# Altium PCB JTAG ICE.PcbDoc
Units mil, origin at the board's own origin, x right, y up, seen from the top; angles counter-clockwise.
Board outline 3085 x 1720 mil, 2 copper layers (Top Layer, Bottom Layer); 45 components, 0 nets, 201 pads, 2 vias.
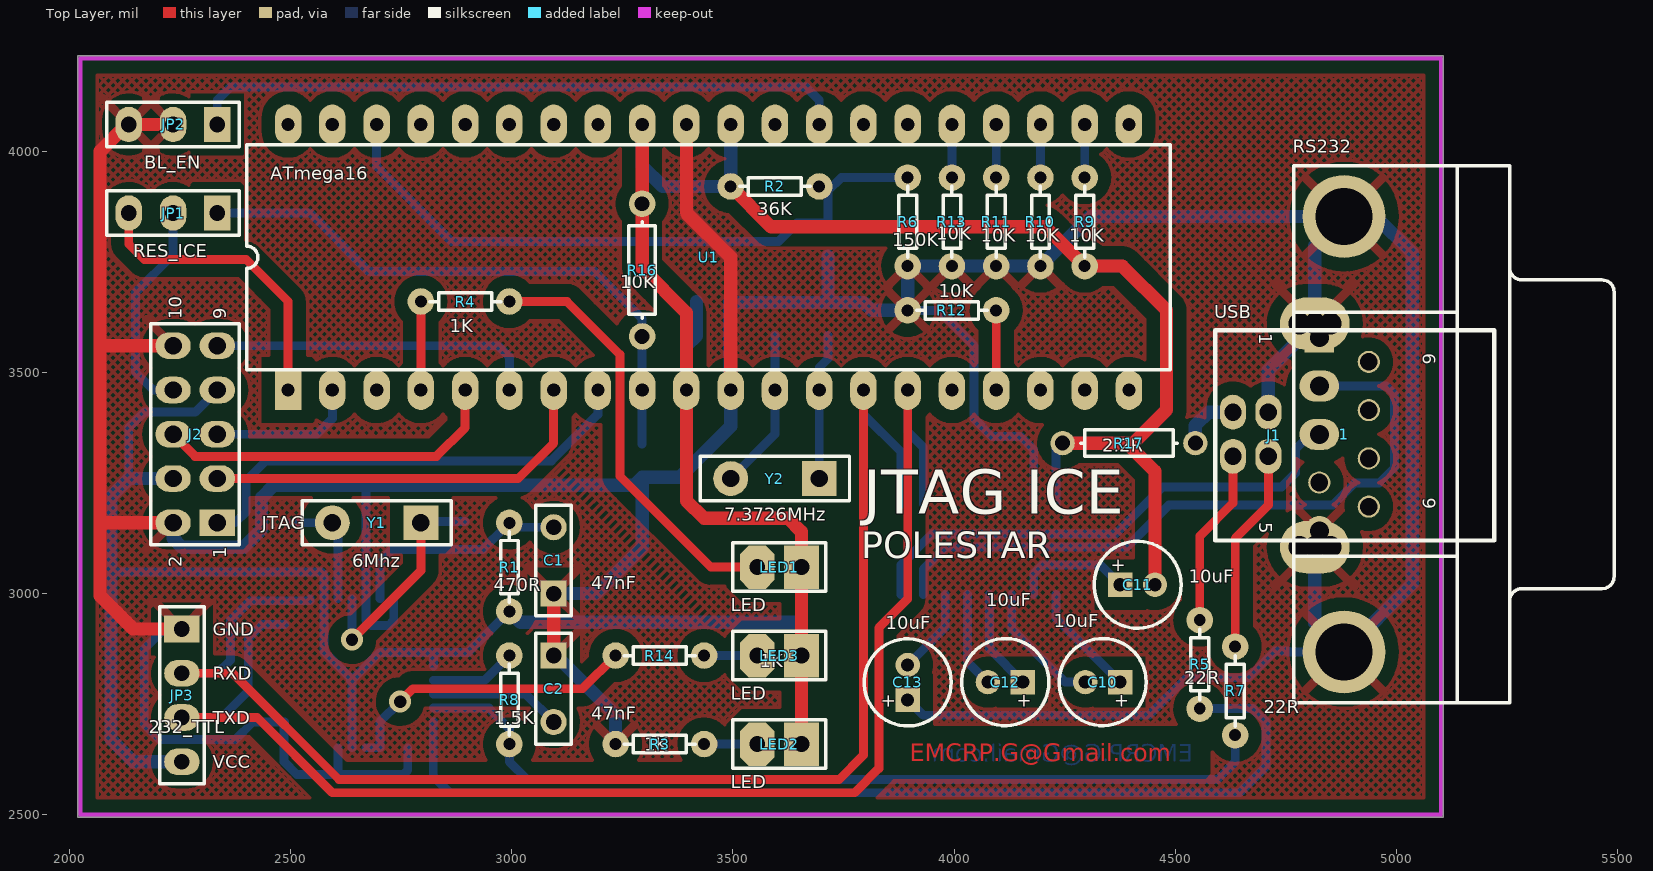
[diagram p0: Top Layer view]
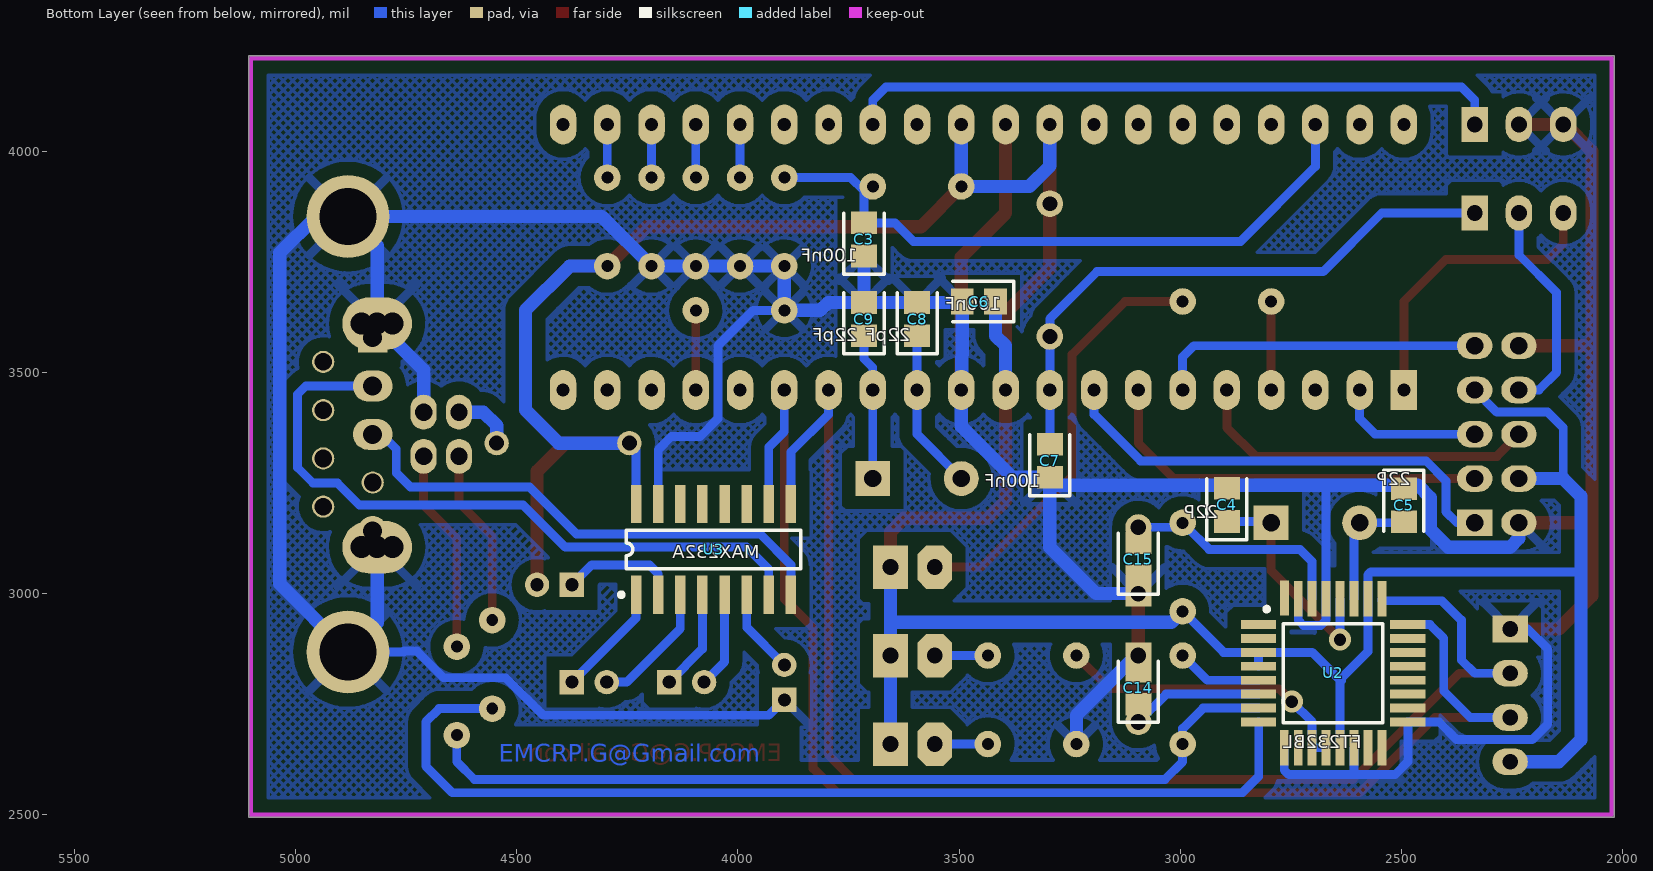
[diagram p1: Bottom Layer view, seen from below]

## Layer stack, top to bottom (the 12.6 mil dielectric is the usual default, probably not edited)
Top Layer: signal copper 1.4
Dielectric: dielectric 12.6, FR-4, Dk 4.8
Bottom Layer: signal copper 1.4

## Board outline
2020,2495 5105,2495 5105,4215 2020,4215

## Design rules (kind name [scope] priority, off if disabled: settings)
Clearance [All] p1: gap=10
PolygonConnect [All] p1: connectstyle=Relief reliefconductorwidth=10 reliefentries=4 polygonreliefangle="90 Angle" airgapwidth=10
RoutingVias [All] p1: holewidth=28 width=50 viastyle="Through Hole" minholewidth=28 minwidth=50 maxholewidth=28 maxwidth=50
SilkscreenOverComponentPads [All] p1: minsilkscreentomaskgap=10
SolderMaskExpansion [All] p1: expansion=4
Width [All] p1: maxlimit=10 minlimit=10 preferedwidth=10
27 further rules are at their usual default settings.

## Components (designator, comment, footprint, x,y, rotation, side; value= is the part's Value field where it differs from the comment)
1 "RS232" DSUB1.385-2H9 5255,3360 r270 top
C1 "47nF" CAP_M_X2 3095,3100 r90 top
C2 "47nF" CAP_M_X2 3095,2760 r270 top
C3 "100nF" CC2012-0805 3715,3800 r90 bottom
C4 "22P" CC2012-0805 2895,3200 r90 bottom
C5 "22P" CC2012-0805 2495,3200 r270 bottom
C6 "100nF" CC2012-0805 3455,3660 r0 bottom
C7 "100nF" CC2012-0805 3295,3300 r90 bottom
C8 "22pF" CC2012-0805 3595,3620 r90 bottom
C9 "22pF" CC2012-0805 3715,3620 r90 bottom
C10 "10uF" CAP_POL1 4375,2800 r180 top
C11 "10uF" CAP_POL1 4375,3020 r0 top
C12 "10uF" CAP_POL1 4155,2800 r180 top
C13 "10uF" CAP_POL1 3895,2760 r90 top
C14 "22pF" CC2012-0805 3095,2787.28 r90 bottom
C15 "47nF" CC2012-0805 3095,3077.28 r90 bottom
J1 "USB" USB_B 5115,3420 r180 top
J2 "JTAG" HDR2X5 2335,3160 r90 top
JP1 "RES_ICE" HDR1X3 2335,3860 r180 top
JP2 "BL_EN" HDR1X3 2335,4060 r180 top
JP3 "232_TTL" HDR1X4 2255,2920 r270 top
LED1 "LED" LED 3655,3060 r180 top
LED2 "LED" LED 3655,2660 r180 top
LED3 "LED" LED 3655,2860 r180 top
R1 "470R" AXIAL-0.2 2995,3060 r270 top
R2 "36K" AXIAL-0.2 3595,3920 r180 top
R3 "1K" AXIAL-0.2 3335,2660 r0 top
R4 "1K" AXIAL-0.2 2895,3660 r0 top
R5 "22R" AXIAL-0.2 4555,2840 r270 top
R6 "150K" AXIAL-0.2 3895,3840 r90 top
R7 "22R" AXIAL-0.2 4635,2780 r270 top
R8 "1.5K" AXIAL-0.2 2995,2760 r90 top
R9 "10K" AXIAL-0.2 4295,3840 r270 top
R10 "10K" AXIAL-0.2 4195,3840 r270 top
R11 "10K" AXIAL-0.2 4095,3840 r270 top
R12 "10K" AXIAL-0.2 3995,3640 r180 top
R13 "10K" AXIAL-0.2 3995,3840 r270 top
R14 "1K" AXIAL-0.2 3335,2860 r180 top
R16 "10K" AXIAL-0.3#1 3295,3680 r90 top
R17 "2.2R" AXIAL-0.3#2 4395,3340 r180 top
U1 "ATmega16" DIP40 3595,4160 r0 top
U2 "FT232BL" 32A 2655,2820 r180 bottom
U3 "MAX232A" NSO16 4055,3100 r180 bottom
Y1 "6Mhz" SPST-2 2695,3160 r180 top
Y2 "7.3726MHz" SPST-2 3595,3260 r180 top

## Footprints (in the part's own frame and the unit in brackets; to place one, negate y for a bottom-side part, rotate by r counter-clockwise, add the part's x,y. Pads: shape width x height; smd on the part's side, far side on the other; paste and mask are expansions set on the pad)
32A [mil]
  rect 80x20 smd: 1(-168.46,110.24) 2(-168.46,78.74) 3(-168.46,47.24) 4(-168.46,15.75) 5(-168.46,-15.75) 6(-168.46,-47.24) 7(-168.46,-78.74) 8(-168.46,-110.24) 17(168.47,-110.24) 18(168.46,-78.74) 19(168.46,-47.24) 20(168.46,-15.75) 21(168.46,15.75) 22(168.46,47.24) 23(168.46,78.74) 24(168.47,110.24)
  rect 20x80 smd: 9(-110.24,-168.46) 10(-78.74,-168.46) 11(-47.24,-168.46) 12(-15.75,-168.46) 13(15.75,-168.46) 14(47.24,-168.46) 15(78.74,-168.46) 16(110.24,-168.46) 25(110.24,168.47) 26(78.74,168.47) 27(47.24,168.47) 28(15.75,168.47) 29(-15.75,168.47) 30(-47.24,168.47) 31(-78.74,168.47) 32(-110,170)
  silkscreen extent -155,-112 112,150
AXIAL-0.2 [mil]
  round 60 hole 27: 1(-100,0) 2(100,0)
  silkscreen extent -80,-20 80,20
AXIAL-0.3#1 [mil]
  round 60 hole 33.47: 1(-99,0) 2(201,0)
  silkscreen extent -58,-30 160,30
AXIAL-0.3#2 [mil]
  round 55.12 hole 33.46: 1(-150,0) 2(150,0)
  silkscreen extent -109,-30 109,30
CAP_M_X2 [mm]
  rect 1.5x1.5 hole 0.9: 1(-2.54,0)
  round 1.5 hole 0.9: 2(1.27,0)
  silkscreen extent -3.81,-1.02 2.54,1.02
CAP_POL1 [mil]
  rect 55x55 hole 29.53: 1(0,0)
  round 55 hole 29.53: 2(78.74,0)
  silkscreen extent -59,-98 138,98
CC2012-0805 [mm]
  rect 1.3x1.5 smd: 1(-0.942,0) 2(0.958,0)
  silkscreen extent -1.99,-1.15 1.51,1.15
DIP40 [mil]
  rect 60x90 hole 30: 1(-1100,-700)
  oval 60x90 hole 30: 2(-1000,-700) 3(-900,-700) 4(-800,-700) 5(-700,-700) 6(-600,-700) 7(-500,-700) 8(-400,-700) 9(-300,-700) 10(-200,-700) 11(-100,-700) 12(0,-700) 13(100,-700) 14(200,-700) 15(300,-700) 16(400,-700) 17(500,-700) 18(600,-700) 19(700,-700) 20(800,-700) 21(800,-100) 22(700,-100) 23(600,-100) 24(500,-100) 25(400,-100) 26(300,-100) 27(200,-100) 28(100,-100) 29(0,-100) 30(-100,-100) 31(-200,-100) 32(-300,-100) 33(-400,-100) 34(-500,-100) 35(-600,-100) 36(-700,-100) 37(-800,-100) 38(-900,-100) 39(-1000,-100) 40(-1100,-100)
  silkscreen extent -1193,-654 893,-146
DSUB1.385-2H9 [mm]
  rect 1.69x1.69 hole 1.09: 1(-5.54,-10.92)
  oval 1.778x2.286 hole 1.09: 2(-2.77,-10.92) 3(0,-10.92)
  round 1.27 hole 1.016: 4(2.77,-10.92) 6(-4.155,-8.08) 7(-1.385,-8.08) 8(1.385,-8.08) 9(4.155,-8.08)
  round 1.69 hole 1.09: 5(5.54,-10.92)
  round 4.76 hole 3.26: 10(-12.495,-9.5) 11(12.495,-9.5)
  silkscreen extent -15.4,-12.4 15.4,6
HDR1X3 [mil]
  rect 60x80 hole 35.43: 1(0,0)
  oval 60x80 hole 35.43: 2(100,0) 3(200,0)
  silkscreen extent -50,-50 250,50
HDR1X4 [mil]
  rect 60x80 hole 35.43: 1(0,0)
  oval 60x80 hole 35.43: 2(100,0) 3(200,0) 4(300,0)
  silkscreen extent -50,-50 350,50
HDR2X5 [mil]
  rect 60x80 hole 39.37: 1(0,0)
  oval 60x80 hole 39.37: 2(0,100) 3(100,0) 4(100,100) 5(200,0) 6(200,100) 7(300,0) 8(300,100) 9(400,0) 10(400,100)
  silkscreen extent -50,-50 450,150
LED [mm]
  rect 2x2.5 hole 0.9: 1(0,0)
  oct 2x2.5 hole 0.9: 2(2.54,0)
  silkscreen extent -1.4,-1.4 3.94,1.4
NSO16 [mm]
  rect 0.6x2.2 smd: 1(-4.445,-2.6) 2(-3.175,-2.6) 3(-1.905,-2.6) 4(-0.635,-2.6) 5(0.635,-2.6) 6(1.905,-2.6) 7(3.175,-2.6) 8(4.445,-2.6) 9(4.445,2.6) 10(3.175,2.6) 11(1.905,2.6) 12(0.635,2.6) 13(-0.635,2.6) 14(-1.905,2.6) 15(-3.175,2.6) 16(-4.445,2.6)
  silkscreen extent -5.42,-2.72 5,1.1
SPST-2 [mm]
  rect 2x2 hole 1: 1(-2.54,0)
  round 2 hole 1: 2(2.54,0)
  silkscreen extent -4.28,-1.27 4.28,1.27
USB_B [mm]
  oval 1.5x2 hole 1: 1(12.319,0.254) 2(12.319,2.794) 3(10.287,2.794) 4(10.287,0.254)
  oval 4x3 hole 1.27: 5(7.62,8.001) 6(7.62,-4.826)
  silkscreen extent -2.67,-4.44 13.33,7.62

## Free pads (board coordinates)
  round 50 hole 50: 1(4780,3105) 2(4850,3105) 3(4850,3610) 4(4780,3610)

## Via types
v1: diameter 50, hole 28, Top Layer to Bottom Layer, 2 vias

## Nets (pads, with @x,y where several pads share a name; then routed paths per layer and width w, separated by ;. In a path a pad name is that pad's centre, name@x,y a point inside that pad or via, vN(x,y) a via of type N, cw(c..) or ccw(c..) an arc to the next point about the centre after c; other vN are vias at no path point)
pads on no net: 1.1 1.2 1.3 1.4 1.5 1.6 1.7 1.8 1.9 1.10 1.11 C1.1 C1.2 C2.1 C2.2 C3.1 C3.2 C4.1 C4.2 C5.1 C5.2 C6.1 C6.2 C7.1 C7.2 C8.1 C8.2 C9.1 C9.2 C10.1 C10.2 C11.1 C11.2 C12.1 C12.2 C13.1 C13.2 C14.1 C14.2 C15.1 C15.2 J1.1 J1.2 J1.3 J1.4 J1.5 J1.6 J2.1 J2.2 J2.3 J2.4 J2.5 J2.6 J2.7 J2.8 J2.9 J2.10 JP1.1 JP1.2 JP1.3 JP2.1 JP2.2 JP2.3 JP3.1 JP3.2 JP3.3 JP3.4 LED1.1 LED1.2 LED2.1 LED2.2 LED3.1 LED3.2 R1.1 R1.2 R2.1 R2.2 R3.1 R3.2 R4.1 R4.2 R5.1 R5.2 R6.1 R6.2 R7.1 R7.2 R8.1 R8.2 R9.1 R9.2 R10.1 R10.2 R11.1 R11.2 R12.1 R12.2 R13.1 R13.2 R14.1 R14.2 R16.1 R16.2 R17.1 R17.2 U1.1 U1.2 U1.3 U1.4 U1.5 U1.6 U1.7 U1.8 U1.9 U1.10 U1.11 U1.12 U1.13 U1.14 U1.15 U1.16 U1.17 U1.18 U1.19 U1.20 U1.21 U1.22 U1.23 U1.24 U1.25 U1.26 U1.27 U1.28 U1.29 U1.30 U1.31 U1.32 U1.33 U1.34 U1.35 U1.36 U1.37 U1.38 U1.39 U1.40 U2.1 U2.2 U2.3 U2.4 U2.5 U2.6 U2.7 U2.8 U2.9 U2.10 U2.11 U2.12 U2.13 U2.14 U2.15 U2.16 U2.17 U2.18 U2.19 U2.20 U2.21 U2.22 U2.23 U2.24 U2.25 U2.26 U2.27 U2.28 U2.29 U2.30 U2.31 U2.32 U3.1 U3.2 U3.3 U3.4 U3.5 U3.6 U3.7 U3.8 U3.9 U3.10 U3.11 U3.12 U3.13 U3.14 U3.15 U3.16 Y1.1 Y1.2 Y2.1 Y2.2
copper on no net: | length 51025.9
  Top Layer w20: 2135,3860 2135,3790 2170,3755 2400,3755 2495,3660 2495,3460 ; 2235,3360 2285,3310 2830,3310 2895,3375 2895,3460 ; 2255,2720 2425,2720 2595,2550 3775,2550 3830,2605 3830,2923 3895,2988 3895,3460 ; 2255,2820 2370,2820 2610,2580 3740,2580 3795,2635 3795,3460 ; 2335,3260 3015,3260 3095,3340 3095,3460 ; v1(2639.25,2896) 2795,3051.75 2795,3160 ; v1(2748,2756) 2777,2785 3160,2785 3235,2860 ; 2795,3460 2795,3660 ; 2995,3660 3125,3660 3245,3540 3245,3265 3450,3060 3555,3060 ; 4095,3460 4095,3640 ; 4555,2940 4555,3130 4630,3205 4630,3310 ; 4635,2880 4635,3125 4710,3200 4710,3310
  Top Layer w30: 2080,3160 2235,3160 ; 2080,3560 2235,3560 ; 2235,4060 2130,4060 2070,4000 2070,2995 2145,2920 2255,2920 ; 3095,2860 3095,3000 ; 3295,4060 3295,3735 3395,3635 3395,3210 3435,3170 3625,3170 3655,3140 3655,2660 ; 3395,4060 3395,3860 3495,3760 3495,3460 ; 3495,3920 3586,3829 4206,3829 4295,3740 4380,3740 4480,3640 4480,3415 4405,3340 4245,3340 ; 4390,3340 4453.74,3276.26 4453.74,3020
  Bottom Layer w20: 2095,3049 2570,3049 2576.26,3042.74 2576.26,2868.74 2640,2805 2702.24,2867.24 2902.24,2867.24 2995,2960 ; 2135,3260 2135,3375 2170,3410 2285,3410 2335,3460 ; 2235,3460 2190,3460 2150,3500 2150,3680 2235,3765 2235,3860 ; 2255,2720 2345,2720 2405,2780 2405,2899 2436.24,2930.24 2486.53,2930.24 ; 2255,2820 2335,2820 2365,2850 2365,2940 2409,2984 2544.76,2984 2544.76,2988.47 ; 2255,2920 2215,2920 2170,2875 2170,2705 2205,2670 2376,2670 2415.76,2709.76 2486.53,2709.76 ; 2335,3160 2375,3160 2400,3185 2400,3255 2445,3300 3090,3300 3195,3405 3195,3460 ; 2335,3360 2560,3360 2595,3395 2595,3460 ; 2335,3560 2970,3560 2995,3535 2995,3460 ; 2335,3860 2545,3860 2677.39,3727.6 3188.39,3727.6 3295,3621 3295,3337.72 ; 2335,4060 2335,4115 2365,4145 3665,4145 3695,4115 3695,4060 ; 2486,2709.76 2486,2620 2515,2591 2755,2591 2765.24,2601.24 2765.24,2651.54 ; 2492.72,3160 2595,3160 ; 2577.28,3177.72 2607.76,3147.24 2607.76,2988.47 ; 2607.76,2591 2607.76,2651.54 ; 2636.26,2803.74 2639.25,2800.75 2639.25,2651.54 ; v1(2639.25,2896) 2639.25,2988.47 ; 2670.75,2651.54 2702.24,2651.54 2702.24,2710.24 v1(2748,2756) ; 2670.75,3237.72 2670.75,2940 2682.75,2928 2721.74,2928 2733.74,2940 2733.74,2988.47 ; 2695,4060 2695,3965 2864,3796 3603.28,3796 3645,3837.72 3715,3837.72 3715,3910 3745,3940 3895,3940 ; 2702.24,2988.47 2702.24,3072.24 2730,3100 2935,3100 2985,3150 3095,3150 ; 2795,3160 2797.91,3162.91 2895,3162.91 ; 2823.46,2709.76 2823,2709.76 2823,2587 2860,2550 4645,2550 4705,2610 4705,2710 4675,2740 4555,2740 ; 2823.46,2741.26 2948.74,2741.26 2995,2695 2995,2620 3035,2580 4595,2580 4635,2620 4635,2680 ; 2823.46,2772.76 3032.24,2772.76 3095,2710 ; 2823.46,2804.25 2939.25,2804.25 2995,2860 ; 2823.46,2835.75 2823.46,2867.24 ; 3435,2660 3555,2660 ; 3435,2860 3555,2860 ; 3495,3260 3595,3360 3595,3460 3595,3582.91 ; 3695,3260 3695,3460 3695,3511 3715,3531 3715,3582.91 ; 3795,3460 3795,3405 3880,3320 3880,3202.36 ; 3880,2997.64 3880,3065 3950,3135 4365,3135 4471,3241 4740,3241 4771.81,3272.81 4771.81,3326.81 4805,3360 4825.08,3360 ; 3895,2760 3930,2725 4440,2725 4525,2810 4665,2810 4725,2870 4755,2870 ; 3895,2838.74 3980,2923.74 3980,2997.64 ; 3895,3460 3895,3366 3930,3331 3930,3202.36 ; 3895,3640 3965,3640 4045,3560 4045,3394.95 4085,3354.95 4150.05,3354.95 4180,3325 4180,3202.36 ; 3930,2997.64 3930,3055 3980,3105 4390,3105 4485,3200 4855,3200 4905,3250 4960,3250 4995,3285 4995,3450 4975.94,3469.06 4825.08,3469.06 ; 3995,3940 3995,4060 ; 4030,2997.64 4030,2846.26 4076.26,2800 ; 4080,2997.64 4080,2875 4155,2800 ; 4095,3940 4095,4060 ; 4130,2997.64 4130,2921 4251,2800 4296.26,2800 ; 4180,2997.64 4180,3045 4200,3065 4330,3065 4375,3020 ; 4195,3940 4195,4060 ; 4230,2997.64 4230,2945 4375,2800 ; 4230,3202.36 4230,3325 4245,3340 ; 4295,3940 4295,4060 ; 4755,2868.07 4880.98,2868.07
  Bottom Layer w30: 2235,3160 2235,3125 2255,3105 2395,3105 2435,3145 2435,3217.09 2462.91,3245 3277.09,3245 3295,3262.91 ; 2235,3260 2135,3260 2095,3220 2095,2670 2145,2620 2255,2620 ; 2335,3160 2350,3160 ; 2995,2960 3020,2935 3655,2935 ; 3095,2865 3235,2725 3235,2660 ; 3095,3000 3190,3000 3295,3105 3295,3262.91 ; 3295,4060 3295,3966 3341,3920 3495,3920 ; 3377.91,3262.91 3295,3262.91 ; 3379.91,3262.91 3495,3378 3495,3460 3492.72,3562.28 3492.72,3660 3495,3657.72 3796,3657.72 3813.72,3640 3895,3640 3895,3740 4195,3740 4306.93,3851.93 4953.07,3851.93 5035,3770 5035,3022.09 4880.98,2868.07 4815,2934.05 4815,3105 ; 3395,3460 3395,3560 3417.91,3582.91 3417.91,3660 ; 3495,3911 3495,4060 ; 3655,2665 3655,3060 ; 3715,3657.72 3715,3762.91 ; 4245,3340 4405,3340 4480,3415 4480,3640 4380,3740 4295,3740 ; 4545,3340 4545,3380 4575,3410 4630,3410 ; 4710,3410 4710,3505 4815,3610 4815,3785.95 4880.98,3851.93

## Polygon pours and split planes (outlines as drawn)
no net on Top Layer "Top Layer-No Net" (hatched 90Degree grid 15 track 8, remove dead copper, pour order 2): 0,0
no net on Bottom Layer "Bottom Layer-No Net" (hatched 90Degree grid 15 track 8, remove dead copper, pour order 4): 0,0

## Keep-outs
Keep-Out Layer:
  lines w10: 2025,2500 2025,4210 5100,4210 5100,2500 2025,2500

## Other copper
Top Layer:
  text "EMCRP.G@Gmail.com" at 3900,2621 h40
Bottom Layer:
  text "EMCRP.G@Gmail.com" at 4540,2620 h40

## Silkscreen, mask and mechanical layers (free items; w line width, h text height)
Top Overlay:
  text "JTAG ICE" at 3795,3180 h100
  text "POLESTAR" at 3790,3080 h60
  text "GND" at 2325,2905 h30
  text "RXD" at 2325,2805 h30
  text "TXD" at 2325,2705 h30
  text "VCC" at 2325,2605 h30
